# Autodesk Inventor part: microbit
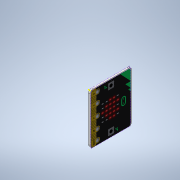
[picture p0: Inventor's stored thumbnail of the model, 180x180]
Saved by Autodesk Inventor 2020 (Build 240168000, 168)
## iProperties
Part Number: microbit
Material: Plastique ABS
Document SubType Name: Modeling
Designer: Buhl
Density: 2.9284 g/cm^3
Appearance: Lisse - Blanc
Mass: 10 g
Surface Area: 45.5791 cm^2
Volume: 3.41484 cm^3
Author: Buhl
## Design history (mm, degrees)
sketch "Esquisse1"
  geometry: L1 (3, 0)-(39, 0); L2 (42, -3)-(42, -48); L3 (39, -51)-(3, -51); L4 (0, -48)-(0, -3); A1 r 2 centre (40, -49) between (40, -51) and (42, -49); A2 r 2 centre (40, -2) between (42, -2) and (40, 0); A3 r 3 centre (39, -48) between (39, -51) and (42, -48); A4 r 3 centre (39, -3) between (42, -3) and (39, 0); A5 r 3 centre (3, -3) between (3, 0) and (0, -3); A6 r 3 centre (3, -48) between (0, -48) and (3, -51); 4 further points
  constraints: 12 point on circle, 12 point on line, 12 tangent, 8 end point, 6 centre point, 4 equal radius, 2 parallel, 1 horizontal, 1 perpendicular
  dimensions: "d0" = 42 distance of point (42, -51) point (0, -51); "d1" = 51 distance of point (42, 0) point (42, -51); "d2" = 2 radius of A1 (derived); "d3" = 3 radius of A3
extrude "Extrusion1" new body sketch "Esquisse1" distance "d4" = 1.6; taper "d5" = 0 deg
sketch "Esquisse2"
  geometry: L1 (0.566, 41.203)-(51.277, 41.203); L2 (51.277, 41.203)-(51.277, 0.803); L3 (51.277, 0.803)-(0.566, 0.803); L4 (0.566, 0.803)-(0.566, 41.203); 1 further point; 1 other entity
  constraints: 2 other
  node "Image1"
sketch "Esquisse3"
  geometry: L1 (-50.817, 41.619)-(-0.018, 41.619); L2 (-0.018, 41.619)-(-0.018, 0.936); L3 (-0.018, 0.936)-(-50.817, 0.936); L4 (-50.817, 0.936)-(-50.817, 41.619); 1 further point; 1 other entity
  constraints: 2 other
  node "Image2"
node "Solide1"
